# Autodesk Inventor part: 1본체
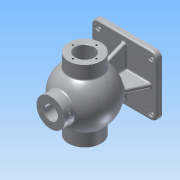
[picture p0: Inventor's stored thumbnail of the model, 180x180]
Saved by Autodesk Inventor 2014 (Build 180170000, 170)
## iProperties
Created: 2017-01
Part Number: 1본체
Material: Aluminum 6061
Document SubType Name: Modeling
Designer: ksu
Density: 2.71 g/cm^3
Appearance: Aluminum - Flat
Mass: 1508.07 g
Surface Area: 1153.94 cm^2
Volume: 556.484 cm^3
Author: ksu
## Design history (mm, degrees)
sketch "Sketch1"
  geometry: L1 (-50.5, -57.5)-(50.5, -57.5); L2 (62.5, -45.5)-(62.5, 45.5); L3 (50.5, 57.5)-(-50.5, 57.5); L4 (-62.5, 45.5)-(-62.5, -45.5); L5 (-62.5, -57.5)-(62.5, 57.5); L6 (62.5, -57.5)-(-62.5, 57.5); A1 r 12 centre (-50.5, 45.5) between (-50.5, 57.5) and (-62.5, 45.5); A2 r 12 centre (-50.5, -45.5) between (-62.5, -45.5) and (-50.5, -57.5); A3 r 12 centre (50.5, -45.5) between (50.5, -57.5) and (62.5, -45.5); A4 r 12 centre (50.5, 45.5) between (62.5, 45.5) and (50.5, 57.5); 1 further point
  constraints: 12 end point, 8 point on circle, 8 point on line, 8 tangent, 4 centre point, 3 equal radius, 2 midpoint, 2 parallel, 1 horizontal, 1 perpendicular
  dimensions: "d0" = 125 distance of L6.end L5.end; "d1" = 115 distance of L5.end L6.start; "d2" = 12 radius of A1
extrude "Extrusion1" new body sketch "Sketch1" distance "d3" = 10; taper "d4" = 0 deg
sketch "Sketch2"
  geometry: L1 (0, 85)-(-53, 85); L2 (-53, 85)-(53, 85); A1 r 53 centre (0, 85) between (53, 85) and (-53, 85); 1 further point
  constraints: 4 end point, 2 point on circle, 1 centre point, 1 collinear, 1 horizontal
  dimensions: "d5" = 106 diameter of A1; "d6" = 85 distance of point (0, 0) L1.start
revolve "Revolution1" sketch "Sketch2" stored, may be unused: angle "d7" = 90 deg
sketch "Sketch3"
  geometry: C1 r 53 at (0, 85) reference; C2 r 31 at (0, 85); 1 further point
  constraints: 1 centre point, 1 coincident
  dimensions: "d8" = 62 diameter of C2
extrude "Extrusion2" join sketch "Sketch3" stored distance "d9" = 136; taper "d10" = 0 deg
workplane "Work Plane1"
sketch "Sketch4"
  geometry: C1 r 27 at (0, 0); 1 further point
  constraints: 1 centre point, 1 coincident
  dimensions: "d12" = 54 diameter of C1
extrude "Extrusion3" join sketch "Sketch4" distance "d13" = 30; taper "d14" = 0 deg
sketch "Sketch5"
  geometry: C1 r 31 at (0, 0) reference; C2 r 17.5 at (0, 0); 1 further point
  constraints: 1 centre point, 1 coincident
  dimensions: "d15" = 35 diameter of C2
extrude "Extrusion4" cut sketch "Sketch5" distance "d16" = 136; taper "d17" = 0 deg
sketch "Sketch6"
  geometry: C1 r 27 at (0, 0) reference; C2 r 13 at (0, 0)
  constraints: 1 centre point, 1 coincident
  dimensions: "d18" = 26 diameter of C2
sketch "Sketch7"
  geometry: L1 (-43, 85)-(43, 85); A1 r 53 centre (0, 85) between (42.988, 116) and (42.988, 54) reference; A2 r 43 centre (0, 85) between (43, 85) and (-43, 85); 1 further point
  constraints: 2 end point, 2 point on circle, 1 centre point, 1 coincident, 1 horizontal
  dimensions: "d19" = 86 diameter of A2
revolve "Revolution2" sketch "Sketch7" stored, may be unused: angle "d20" = 90 deg
sketch "Sketch8"
  geometry: 1 further point
extrude "Extrusion5" cut sketch "Sketch6" distance "d21" = 30; taper "d22" = 0 deg
sketch "Sketch9"
  geometry: 1 further point
sketch "Sketch10"
  geometry: L1 (45.5, 10)-(-45.5, 10) reference; L2 (57.5, 10)-(47.5, 10); L3 (47.5, 10)-(32.011, 48.336); L4 (0, 0)-(0, 23.921); L5 (57.5, 0)-(57.5, 10) reference; L6 (-47.5, 10)-(-32.011, 48.336); L7 (-57.5, 10)-(-45.5, 10); L8 (-47.5, 10)-(47.5, 10); A1 r 53 centre (0, 85) between (42.988, 116) and (42.988, 54) reference; A2 r 48.672 centre (0, 85) between (32.011, 48.336) and (-32.011, 48.336); 2 further points
  constraints: 12 end point, 3 point on circle, 3 point on line, 2 symmetric about line, 1 centre point, 1 coincident, 1 collinear, 1 perpendicular
  dimensions: "d23" = 10 distance of L2.start L2.end; "d24" = 22 deg angle of L5 L3
extrude "Extrusion6" join sketch "Sketch10" stored distance "d25" = 8; taper "d26" = 0 deg
sketch "Sketch12"
  geometry: L1 (50.5, 10)-(-50.5, 10) reference; L2 (62.5, 0)-(62.5, 10) reference; L3 (62.5, 10)-(52.5, 10); L4 (52.5, 10)-(35.258, 52.676); L5 (-62.5, 10)-(-52.5, 10); L6 (-52.5, 10)-(-33.514, 50.872); L7 (-52.5, 10)-(52.5, 10); L8 (-52.5, 10)-(52.5, 10); A1 r 53 centre (0, 85) between (-27, 130.607) and (27, 130.607) reference; A2 r 47.833 centre (0, 85) between (-33.514, 50.872) and (35.258, 52.676); 1 further point
  constraints: 12 end point, 2 collinear, 2 point on circle, 1 centre point, 1 coincident, 1 perpendicular
  dimensions: "d27" = 10 distance of L2.end L3.end; "d83" = 22 deg angle of L2 L4
extrude "Extrusion7" join sketch "Sketch12" stored distance "d28" = 8; taper "d29" = 0 deg
sketch "Sketch13"
  geometry: C1 r 31 at (0, 0) reference; A1 r 24 centre (0, 0) between (0, 24) and (24, 0); 3 further points
  constraints: 4 point on circle, 1 centre point, 1 coincident
  dimensions: "d30" = 48 diameter of A1
hole "Hole1" sketch "Sketch13" at (24, 0), (0, 24), (-24, 0), (0, -24) diameter "d31" = 3.459; stored, may be unused: countersink angle "d35" = 90 deg, drill point angle "d37" = 118 deg; dims "d32" = 16, "d33" = 4, "d34" = 2, "d36" = 19
sketch "Sketch14"
  geometry: C1 r 31 at (0, 0) reference; A1 r 22.5 centre (0, 0) between (0, 22.5) and (22.5, 0); 3 further points
  constraints: 4 point on circle, 1 centre point, 1 coincident
  dimensions: "d38" = 45 diameter of A1
hole "Hole2" sketch "Sketch14" at (-22.5, 0), (0, -22.5), (22.5, 0), (0, 22.5) diameter "d39" = 3.459; stored, may be unused: countersink angle "d43" = 90 deg, drill point angle "d45" = 118 deg; dims "d40" = 12, "d41" = 4, "d42" = 2, "d44" = 15
sketch "Sketch15"
  geometry: L1 (-68, 102.5)-(-39.278, 102.5) reference; L2 (-68, 67.5)-(-39.278, 67.5) reference; L3 (-68, 102.5)-(-52, 102.5); L4 (-52, 102.5)-(-52, 103.5); L5 (-52, 103.5)-(-50.25, 103.5); L6 (-50.25, 103.5)-(-50.25, 85); L7 (0, 85)-(-100.25, 85); L8 (-52, 102.5)-(-52, 85); L9 (-50.25, 85)-(-50.25, 103.5); L10 (-68, 67.5)-(-68, 102.5) reference; 1 further point
  constraints: 14 end point, 4 perpendicular, 3 point on line, 1 collinear, 1 parallel
  dimensions: "d46" = 16 distance of L1.start L3.end; "d47" = 37 diameter of L5 L7; "d48" = 1.75 distance between parallel lines of L8 L6; "d49" = 16 distance between parallel lines of L10 L8 (derived)
revolve "Revolution3" sketch "Sketch15" stored, may be unused: angle "d50" = 90 deg
sketch "Sketch16"
  geometry: 1 further point
sketch "Sketch17"
  geometry: C1 r 27 at (0, 0) reference; A1 r 20 centre (0, 0) between (0, 20) and (20, 0); 2 further points
  constraints: 4 point on circle, 1 centre point, 1 coincident
  dimensions: "d51" = 40 diameter of A1
hole "Hole3" sketch "Sketch17" at (0, -20), (20, 0), (0, 20), (-20, 0) diameter "d52" = 3.459; stored, may be unused: countersink angle "d56" = 90 deg, drill point angle "d58" = 118 deg; dims "d53" = 9, "d54" = 4, "d55" = 2, "d57" = 11
sketch "Sketch18"
  geometry: A1 r 12 centre (-50.5, -45.5) between (-62.5, -45.5) and (-50.5, -57.5) reference; A2 r 12 centre (50.5, -45.5) between (50.5, -57.5) and (62.5, -45.5) reference; A3 r 12 centre (50.5, 45.5) between (62.5, 45.5) and (50.5, 57.5) reference; A4 r 12 centre (-50.5, 45.5) between (-50.5, 57.5) and (-62.5, 45.5) reference; 5 further points
  constraints: 4 coincident
  dimensions: "d59" = 101 distance of point (50.5, 45.5) point (-50.5, 45.5) (derived); "d60" = 91 distance of point (50.5, -45.5) point (50.5, 45.5) (derived)
hole "Hole4" sketch "Sketch18" at (-50.5, -45.5), (-50.5, 45.5), (50.5, -45.5), (50.5, 45.5) diameter "d61" = 8; stored, may be unused: countersink angle "d65" = 90 deg, drill point angle "d67" = 118 deg; dims "d62" = 9, "d63" = 12, "d64" = 3, "d66" = 10
chamfer "Chamfer1" distance "d68" = 1; stored, may be unused: second distance "d69" = 2, angle "d70" = 45 deg
fillet "Fillet1" dims "d71" = 3
fillet "Fillet4" dims "d74" = 3
fillet "Fillet5" dims "d75" = 3
fillet "Fillet6" dims "d76" = 3
fillet "Fillet7" dims "d77" = 3
fillet "Fillet8" dims "d78" = 3
sketch "Sketch19"
  geometry: L1 (-139.383, 31.579)-(-139.383, 59.421); L2 (-139.383, 59.421)-(-140.617, 59.421); L3 (-140.617, 59.421)-(-140.617, 31.579); L4 (-140.617, 31.579)-(-139.383, 31.579); L5 (-140, 31.579)-(-140, 59.421); L6 (-139.383, 45.5)-(-140.617, 45.5); L7 (-150, 18.5)-(-150, 72.5) reference; L8 (-150, 18.5)-(-132.286, 18.5) reference; 1 further point
  constraints: 4 end point, 4 midpoint, 2 other
  dimensions: "d79" = 27 distance between parallel lines of L8 L6; "d80" = 10 distance between parallel lines of L7 L5
emboss "Emboss1" sketch "Sketch19" dims "d0" = 125, "d1" = 115, "d2" = 12, "d7" = 90 deg, "d81" = 0.5, "d82" = 0
body "Solid1"
